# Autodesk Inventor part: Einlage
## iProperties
Created: 2005-01
Part Number: Einlage
Material: Standard
Document SubType Name: Modeling
Designer: ap
Manufacturer: Standard
Standards Organization: Custom
Author: ap
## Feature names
1. Basis1
